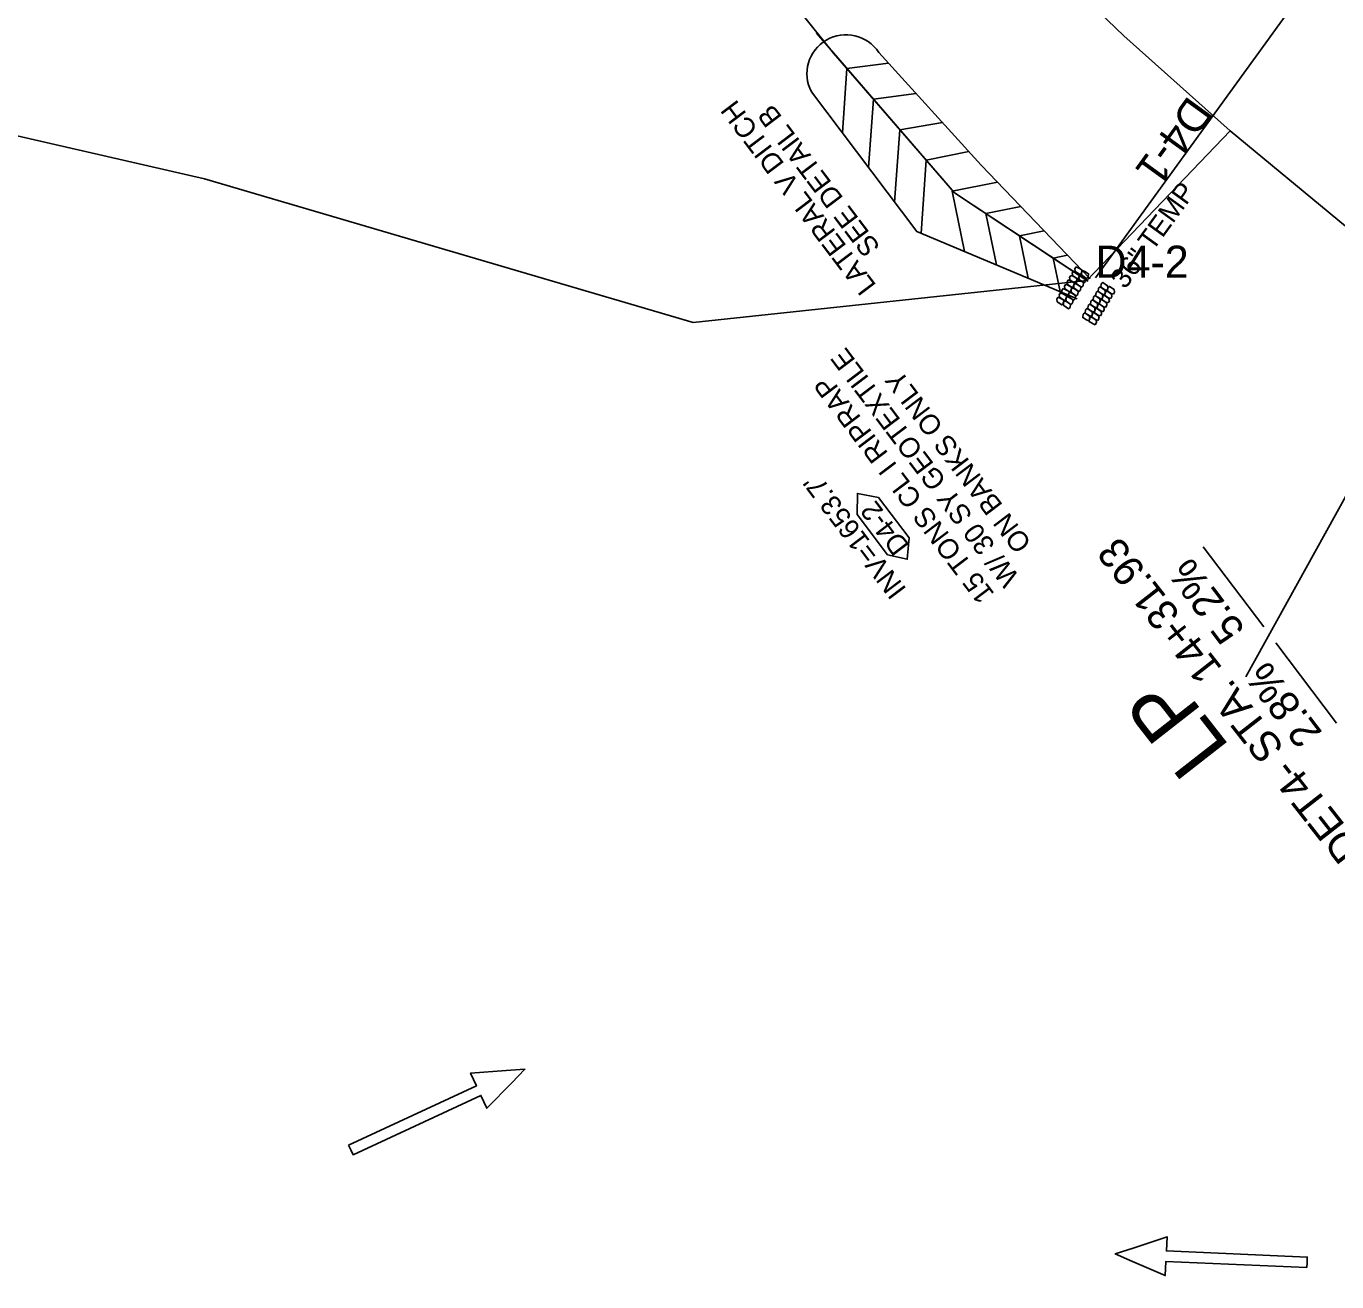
# Model space of a CAD drawing. Extents: x 465700 to 483515, y 488970 to 507540.
# Drawn here: x 476301 to 476627.3, y 500377.8 to 500690.3 of the extents above; entities that cross this region are included whole.
import ezdxf

# ---------------------------------------------------------------- set-up
doc = ezdxf.new("R2010")
doc.units = 0
for name, color, linetype in [('Default', 7, 'Continuous'), ('Exist Plan Preparation Drainage Flow Arrows', 7, 'Continuous'), ('Exist Plan Preparation Watershed Blue', 7, 'Continuous'), ('Prop Drainage Structure Box Number Symbol CELL', 7, 'Continuous'), ('Prop Drainage Structure Pipe RCP 15in Class III', 7, 'Continuous'), ('Prop Drainage Structure Pipe RCP 36in Class III', 7, 'Continuous'), ('Prop Drainage Structure Pipe RCP 36in Class III Label', 7, 'Continuous'), ('Prop Drainage Structure Tops and Inverts LABEL', 7, 'Continuous'), ('Prop Earthen Structure Head Ditch', 7, 'Continuous'), ('Prop Erosion Embankment Toe Protection Label', 7, 'Continuous'), ('Prop Erosion Rip Rap Pad at Outlet Label', 7, 'Continuous'), ('Prop Erosion Rip Rap Pad Outlet for Jurisdictional Stream CELL', 7, 'Continuous'), ('Prop Plan Preparation Sag', 7, 'Continuous'), ('Prop Plan Preparation Sag Label', 7, 'Continuous'), ('Scratch_Level_8', 7, 'Continuous')]:
    doc.layers.add(name, color=color, linetype=linetype)

# ---------------------------------------------------------------- blocks, each defined once
blk = doc.blocks.new('Existing ground flow arrow')
at = {"layer": 'Default'}
blk.add_line((2.5, -4.33), (2.5, -4.33), dxfattribs=at)
blk.add_lwpolyline([(-1.29, -47.2), (-1.28, -12.53), (-4.77, -12.53), (-1.65, -4.33), (0, 0), (1.65, -4.33), (4.78, -12.53), (1.28, -12.52), (1.29, -47.19), (0, -47.2)], close=True, dxfattribs=at)

msp = doc.modelspace()

# ---------------------------------------------------------------- linework, layer by layer
at = {"layer": 'Exist Plan Preparation Watershed Blue'}
for points in [[(476209, 500683.6), (476345.39, 500652.36), (476467.07, 500616.53), (476565.07, 500627.06), (476600.68, 500664.31), (476574.27, 500687.93), (476537.67, 500723.12), (476510.19, 500751.77), (476483.11, 500782.17), (476453.04, 500818.7), (476434.2, 500842.61), (476385.69, 500904.17), (476387.26, 500905.41), (476372.86, 500924.02), (476358.8, 500942.89), (476340.03, 500969.19), (476316.98, 501003.43), (476294.62, 501039.29)], [(476537.67, 500723.12), (476574.27, 500687.93), (476600.68, 500664.31), (476629.44, 500640.58), (476660.48, 500616.5), (476665.75, 500612.5), (476684.89, 500598.68), (476704.31, 500585.26), (476724.01, 500572.25), (476725.16, 500573.92), (476745.2, 500561.65), (476765.23, 500549.24), (476785.68, 500537.54), (476796.4, 500556.75), (476816.75, 500545.66), (476837.37, 500534.26), (476847.59, 500528.4), (476917.86, 500472.75)]]:
    msp.add_lwpolyline(points, dxfattribs=at)
at = {"layer": 'Prop Drainage Structure Box Number Symbol CELL'}
msp.add_lwpolyline([(476515.45, 500558.75), (476507.84, 500568.8), (476507.95, 500574.02), (476513.18, 500573.04), (476520.79, 500562.99), (476520.35, 500557.64), (476515.45, 500558.75)], dxfattribs=at)
at = {"layer": 'Prop Drainage Structure Pipe RCP 15in Class III'}
msp.add_line((476459.56, 500736.43), (476502.02, 500683.58), dxfattribs=at)
at = {"layer": 'Prop Drainage Structure Pipe RCP 36in Class III'}
msp.add_line((476626.52, 500709.58), (476567.2, 500627.7), dxfattribs=at)
at = {"layer": 'Prop Earthen Structure Head Ditch'}
for points in [[(476497.72, 500688.55), (476532.08, 500648.88), (476565.07, 500627.06)], [(476502.02, 500683.58), (476532.08, 500648.88), (476565.4, 500626.85)], [(476513.23, 500683.81), (476538.74, 500655.76), (476565.91, 500627.46)], [(476504.19, 500663.77), (476505.33, 500679.76), (476515.65, 500681.15)], [(476562.66, 500622.48), (476522.71, 500639.21), (476496.47, 500674)], [(476510.69, 500655.14), (476511.91, 500672.16), (476522.57, 500673.55)], [(476517.2, 500646.52), (476518.49, 500664.56), (476529.11, 500666.36)], [(476523.77, 500638.77), (476525.07, 500656.97), (476535.71, 500659.1)], [(476534.59, 500634.24), (476531.54, 500649.24), (476542.8, 500651.53)], [(476542.52, 500630.91), (476539.92, 500643.69), (476548.63, 500645.47)], [(476550.45, 500627.59), (476548.3, 500638.15), (476554.45, 500639.4)], [(476558.38, 500624.27), (476556.68, 500632.61), (476560.27, 500633.34)]]:
    msp.add_lwpolyline(points, dxfattribs=at)
msp.add_arc((476505.1, 500678.48), 9.72, 33.237, 207.4508, dxfattribs=at)
at = {"layer": 'Prop Erosion Rip Rap Pad Outlet for Jurisdictional Stream CELL'}
msp.add_line((476567.2, 500627.7), (476567.2, 500627.7), dxfattribs=at)
msp.add_line((476567.2, 500627.7), (476567.2, 500627.7), dxfattribs=at)
for points in [[(476561.06, 500628.29), (476561.62, 500628.06), (476562.54, 500627.5), (476562.45, 500626.67), (476562.05, 500626.33), (476560.87, 500627.14), (476560.77, 500627.79), (476561.06, 500628.29)], [(476561.71, 500629.37), (476562.27, 500629.14), (476563.19, 500628.59), (476563.1, 500627.75), (476562.69, 500627.41), (476561.52, 500628.22), (476561.41, 500628.87), (476561.71, 500629.37)], [(476562.35, 500630.46), (476562.91, 500630.21), (476563.83, 500629.66), (476563.75, 500628.84), (476563.34, 500628.5), (476562.16, 500629.29), (476562.05, 500629.94), (476562.35, 500630.46)], [(476563.34, 500628.4), (476563.9, 500628.17), (476564.82, 500627.62), (476564.73, 500626.78), (476564.33, 500626.44), (476563.15, 500627.25), (476563.04, 500627.89), (476563.34, 500628.4)], [(476563.99, 500629.48), (476564.54, 500629.24), (476565.46, 500628.69), (476565.38, 500627.87), (476564.97, 500627.53), (476563.79, 500628.32), (476563.68, 500628.97), (476563.99, 500629.48)], [(476559.13, 500625.06), (476559.69, 500624.82), (476560.62, 500624.27), (476560.53, 500623.44), (476560.12, 500623.1), (476558.94, 500623.9), (476558.83, 500624.55), (476559.13, 500625.06)], [(476559.78, 500626.14), (476560.33, 500625.9), (476561.26, 500625.35), (476561.17, 500624.52), (476560.77, 500624.18), (476559.58, 500624.98), (476559.47, 500625.63), (476559.78, 500626.14)], [(476560.42, 500627.21), (476560.97, 500626.97), (476561.9, 500626.42), (476561.81, 500625.6), (476561.41, 500625.26), (476560.22, 500626.05), (476560.12, 500626.71), (476560.42, 500627.21)], [(476561.41, 500625.17), (476561.97, 500624.92), (476562.89, 500624.37), (476562.8, 500623.55), (476562.4, 500623.21), (476561.21, 500624), (476561.1, 500624.65), (476561.41, 500625.17)], [(476562.05, 500626.24), (476562.61, 500626), (476563.53, 500625.45), (476563.45, 500624.62), (476563.04, 500624.28), (476561.85, 500625.08), (476561.75, 500625.74), (476562.05, 500626.24)], [(476562.69, 500627.31), (476563.25, 500627.08), (476564.18, 500626.53), (476564.09, 500625.7), (476563.68, 500625.36), (476562.5, 500626.16), (476562.4, 500626.82), (476562.69, 500627.31)], [(476569.37, 500623.48), (476568.81, 500623.71), (476567.89, 500624.26), (476567.98, 500625.09), (476568.38, 500625.43), (476569.56, 500624.63), (476569.66, 500623.97), (476569.37, 500623.48)], [(476570.01, 500624.55), (476569.46, 500624.79), (476568.53, 500625.34), (476568.62, 500626.17), (476569.02, 500626.51), (476570.21, 500625.71), (476570.31, 500625.05), (476570.01, 500624.55)], [(476571.64, 500623.58), (476571.09, 500623.82), (476570.16, 500624.37), (476570.25, 500625.19), (476570.65, 500625.53), (476571.84, 500624.74), (476571.94, 500624.08), (476571.64, 500623.58)], [(476557.85, 500622.9), (476558.4, 500622.66), (476559.32, 500622.1), (476559.24, 500621.28), (476558.83, 500620.94), (476557.65, 500621.74), (476557.55, 500622.39), (476557.85, 500622.9)], [(476558.49, 500623.97), (476559.05, 500623.74), (476559.97, 500623.19), (476559.88, 500622.35), (476559.47, 500622.02), (476558.29, 500622.82), (476558.19, 500623.48), (476558.49, 500623.97)], [(476559.48, 500621.93), (476560.03, 500621.68), (476560.95, 500621.13), (476560.87, 500620.31), (476560.46, 500619.97), (476559.28, 500620.76), (476559.18, 500621.42), (476559.48, 500621.93)], [(476560.12, 500623), (476560.68, 500622.77), (476561.6, 500622.22), (476561.51, 500621.38), (476561.1, 500621.04), (476559.93, 500621.85), (476559.82, 500622.5), (476560.12, 500623)], [(476560.76, 500624.08), (476561.33, 500623.85), (476562.25, 500623.3), (476562.16, 500622.47), (476561.75, 500622.13), (476560.57, 500622.93), (476560.46, 500623.58), (476560.76, 500624.08)], [(476567.44, 500620.23), (476566.88, 500620.48), (476565.96, 500621.03), (476566.04, 500621.85), (476566.45, 500622.19), (476567.63, 500621.4), (476567.74, 500620.74), (476567.44, 500620.23)], [(476568.08, 500621.31), (476567.52, 500621.55), (476566.6, 500622.1), (476566.68, 500622.93), (476567.09, 500623.27), (476568.27, 500622.47), (476568.38, 500621.82), (476568.08, 500621.31)], [(476568.72, 500622.39), (476568.16, 500622.62), (476567.24, 500623.18), (476567.33, 500624.01), (476567.74, 500624.35), (476568.91, 500623.54), (476569.02, 500622.9), (476568.72, 500622.39)], [(476569.71, 500620.33), (476569.15, 500620.58), (476568.23, 500621.13), (476568.31, 500621.95), (476568.72, 500622.29), (476569.91, 500621.5), (476570.01, 500620.85), (476569.71, 500620.33)], [(476570.35, 500621.42), (476569.79, 500621.65), (476568.87, 500622.2), (476568.96, 500623.04), (476569.37, 500623.38), (476570.55, 500622.57), (476570.66, 500621.92), (476570.35, 500621.42)], [(476571, 500622.5), (476570.44, 500622.74), (476569.52, 500623.29), (476569.61, 500624.12), (476570.01, 500624.46), (476571.19, 500623.65), (476571.3, 500623), (476571, 500622.5)], [(476565.5, 500616.99), (476564.95, 500617.24), (476564.02, 500617.79), (476564.11, 500618.61), (476564.51, 500618.95), (476565.7, 500618.16), (476565.81, 500617.51), (476565.5, 500616.99)], [(476566.15, 500618.08), (476565.59, 500618.31), (476564.66, 500618.86), (476564.75, 500619.69), (476565.16, 500620.03), (476566.34, 500619.23), (476566.45, 500618.58), (476566.15, 500618.08)], [(476566.79, 500619.16), (476566.23, 500619.39), (476565.31, 500619.94), (476565.4, 500620.78), (476565.81, 500621.12), (476566.99, 500620.31), (476567.09, 500619.66), (476566.79, 500619.16)], [(476567.78, 500617.1), (476567.22, 500617.34), (476566.3, 500617.89), (476566.39, 500618.72), (476566.79, 500619.06), (476567.97, 500618.26), (476568.08, 500617.61), (476567.78, 500617.1)], [(476568.43, 500618.19), (476567.87, 500618.42), (476566.94, 500618.97), (476567.03, 500619.8), (476567.44, 500620.14), (476568.62, 500619.34), (476568.72, 500618.68), (476568.43, 500618.19)], [(476569.07, 500619.26), (476568.51, 500619.5), (476567.59, 500620.06), (476567.67, 500620.88), (476568.08, 500621.22), (476569.27, 500620.42), (476569.37, 500619.77), (476569.07, 500619.26)], [(476567.13, 500616.02), (476566.58, 500616.26), (476565.66, 500616.81), (476565.74, 500617.64), (476566.15, 500617.98), (476567.33, 500617.18), (476567.44, 500616.53), (476567.13, 500616.02)]]:
    msp.add_lwpolyline(points, dxfattribs=at)
at = {"layer": 'Prop Plan Preparation Sag'}
msp.add_line((476661.71, 500631.77), (476604.66, 500528.38), dxfattribs=at)
at = {"layer": 'Prop Plan Preparation Sag Label'}
for p, q in [((476609.07, 500540.77), (476593.99, 500560.71)), ((476612.09, 500536.79), (476627.18, 500516.85))]:
    msp.add_line(p, q, dxfattribs=at)
at = {"layer": 'Scratch_Level_8'}
msp.add_line((476626.52, 500709.58), (476567.2, 500627.7), dxfattribs=at)

# ---------------------------------------------------------------- block references
at = {"layer": 'Exist Plan Preparation Drainage Flow Arrows', "yscale": 1.0124070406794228}
for p, xscale, rotation in [((476425.17, 500430.69), 1.0124070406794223, -65.10543138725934), ((476572.12, 500384.7), 1.0124070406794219, 87.47922145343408)]:
    msp.add_blockref('Existing ground flow arrow', p, dxfattribs=dict(at, xscale=xscale, rotation=rotation))

# ---------------------------------------------------------------- texts
at = {"layer": 'Prop Drainage Structure Box Number Symbol CELL'}
msp.add_text('D4-2', height=5, rotation=127.1208, dxfattribs=at).set_placement((476521.11, 500561.04))
at = {"layer": 'Prop Drainage Structure Pipe RCP 36in Class III Label'}
msp.add_text('36" TEMP', height=5, rotation=54.0756, dxfattribs=at).set_placement((476574.6, 500624.66))
at = {"layer": 'Prop Drainage Structure Tops and Inverts LABEL'}
msp.add_text("INV=1653.7'", height=5, rotation=127.1236, dxfattribs=at).set_placement((476520.33, 500550.17))
at = {"layer": 'Prop Erosion Embankment Toe Protection Label'}
for s, p in [('LATERAL V DITCH', (476512.79, 500625.82)), ('SEE DETAIL B', (476513.8, 500635.35))]:
    msp.add_text(s, height=5, rotation=127.1092, dxfattribs=at).set_placement(p)
at = {"layer": 'Prop Erosion Rip Rap Pad at Outlet Label'}
for s, p in [('W/ 30 SY GEOTEXTILE', (476548.46, 500553.17)), ('15 TONS CL I RIPRAP', (476542.21, 500549.01)), ('ON BANKS ONLY', (476551.48, 500561.61))]:
    msp.add_text(s, height=5, rotation=127.1236, dxfattribs=at).set_placement(p)
at = {"layer": 'Prop Plan Preparation Sag Label'}
for s, height, rotation, p in [('-L_DET4- STA. 14+31.93', 7.5, 128.006, (476642.93, 500474.25)), ('5.2%', 7.5, 127.1236, (476604.68, 500540.24)), ('2.8%', 7.5, 127.1236, (476623.86, 500514.45)), ('LP', 15, 128.0094, (476600.89, 500510.81))]:
    msp.add_text(s, height=height, rotation=rotation, dxfattribs=at).set_placement(p)
at = {"layer": 'Scratch_Level_8'}
msp.add_text('D4-1', height=8, rotation=234.0756, dxfattribs=at).set_placement((476590.38, 500673.33))
msp.add_text('D4-2', height=8, dxfattribs=at).set_placement((476567.2, 500627.7))

doc.saveas('drawing.dxf')
